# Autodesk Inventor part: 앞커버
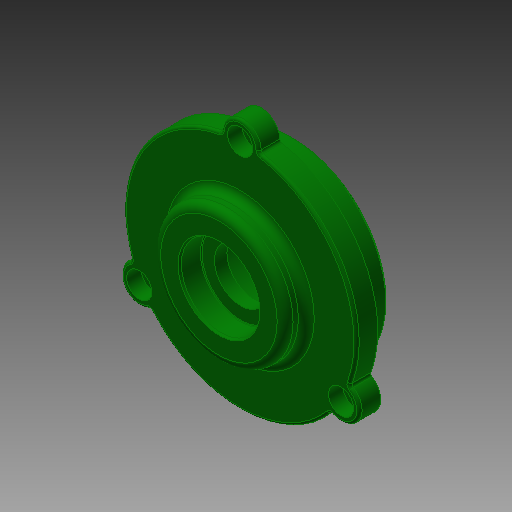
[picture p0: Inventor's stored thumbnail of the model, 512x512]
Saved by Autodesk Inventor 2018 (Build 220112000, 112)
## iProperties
Created: 2016-05
Part Number: 앞커버
Document SubType Name: Modeling
Designer: mduedu
Density: 2.71 g/cm^3
Material: 알루미늄 6061
Appearance: 진녹색
Author: mduedu
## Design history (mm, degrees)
sketch "스케치1"
  geometry: C1 r 36 at (0, 0); C2 r 44 at (0, 0); 1 further point
  constraints: 2 centre point, 2 coincident
  dimensions: "d33" = 88 diameter of C2; "d34" = 72 diameter of C1
extrude "돌출1" new body sketch "스케치1" distance "d0" = 8; taper "d1" = 0 deg
extrude "돌출2" join sketch "스케치1" distance "d2" = 8; taper "d3" = 0 deg; dims "d35" = 12, "d36" = 0
sketch "스케치6"
  geometry: C1 r 25 at (0, 0); 2 further points
  constraints: 2 coincident, 1 centre point
  dimensions: "d42" = 50 diameter of C1
extrude "돌출4" join sketch "스케치6" distance "d43" = 8; taper "d44" = 0 deg
sketch "스케치9"
  geometry: C1 r 7 at (0, 44); 2 further points
  constraints: 2 vertical alignment, 1 centre point, 1 other
  dimensions: "d70" = 14 diameter of C1
extrude "돌출5" join sketch "스케치9" stored distance "d71" = 10; taper "d72" = 0 deg
fillet "모깎기9" dims "d76" = 1
sketch "스케치10"
  geometry: C1 r 25 at (0, 0) reference; A1 r 1 centre (-42.349, -15.218) between (-41.818, -16.066) and (-41.408, -14.88) reference; A2 r 7 centre (-38.105, -22) between (-41.818, -16.066) and (-34.823, -28.183) reference; A3 r 1 centre (-34.354, -29.066) between (-33.59, -28.42) and (-34.823, -28.183) reference; A4 r 44 centre (0, 0) between (-33.59, -28.42) and (33.59, -28.42) reference; A5 r 1 centre (34.354, -29.066) between (34.823, -28.183) and (33.59, -28.42) reference; A6 r 7 centre (38.105, -22) between (34.823, -28.183) and (41.818, -16.066) reference; A7 r 1 centre (42.349, -15.218) between (41.408, -14.88) and (41.818, -16.066) reference; A8 r 44 centre (0, 0) between (41.408, -14.88) and (7.817, 43.3) reference; A9 r 1 centre (7.995, 44.284) between (6.996, 44.249) and (7.817, 43.3) reference; A10 r 7 centre (0, 44) between (6.996, 44.249) and (-6.996, 44.249) reference; A11 r 1 centre (-7.995, 44.284) between (-7.817, 43.3) and (-6.996, 44.249) reference; A12 r 44 centre (0, 0) between (-7.817, 43.3) and (-41.408, -14.88) reference; 4 further points
  constraints: 3 coincident
hole "구멍3" sketch "스케치10" at (0, 44), (-38.105, -22), (38.105, -22) diameter "d77" = 5.5; stored, may be unused: countersink angle "d81" = 90 deg, drill point angle "d83" = 118 deg; dims "d78" = 6, "d79" = 9.5, "d80" = 5.4, "d82" = 8
fillet "모깎기10" dims "d84" = 1
fillet "모깎기7" dims "d68" = 3
fillet "모깎기8" dims "d69" = 3
sketch "스케치4"
  geometry: L1 (0, -12)-(0, 16); L2 (-20, -12)-(-20, 0); L3 (-20, 0)-(-15, 0); L4 (-15, 0)-(-15, 3); L5 (-15, 3)-(-10, 3); L6 (-10, 3)-(-10, 7.7); L7 (-10, 7.7)-(-15, 7.7); L8 (-15, 7.7)-(-15, 16); L9 (36, -12)-(-36, -12) reference; L10 (25, 16)-(-25, 16) reference; 1 further point
  constraints: 16 end point, 6 parallel, 3 point on line, 2 midpoint, 1 perpendicular, 1 vertical
  dimensions: "d15" = 40 diameter of L2 L1; "d16" = 30 diameter of L8 L1; "d18" = 12 distance of L2.start L2.end; "d19" = 3 distance of L3.end L4.end; "d20" = 30 diameter of L4 L1; "d21" = 20 diameter of L6 L1; "d45" = 8.3 distance of L7.end L8.end
revolve "회전1" sketch "스케치4" stored, may be unused: angle "d22" = 90 deg
fillet "모깎기2" dims "d23" = 3
fillet "모깎기3" dims "d24" = 0.3
chamfer "모따기2" distance "d46" = 1; stored, may be unused: second distance "d47" = 2, angle "d48" = 45 deg
chamfer "모따기3" distance "d64" = 0.8; stored, may be unused: second distance "d65" = 2, angle "d66" = 30 deg
node "솔리드1"
pattern_circular "원형 패턴1" dims angle "d74" = 360 deg
node "투영된 루프1"
